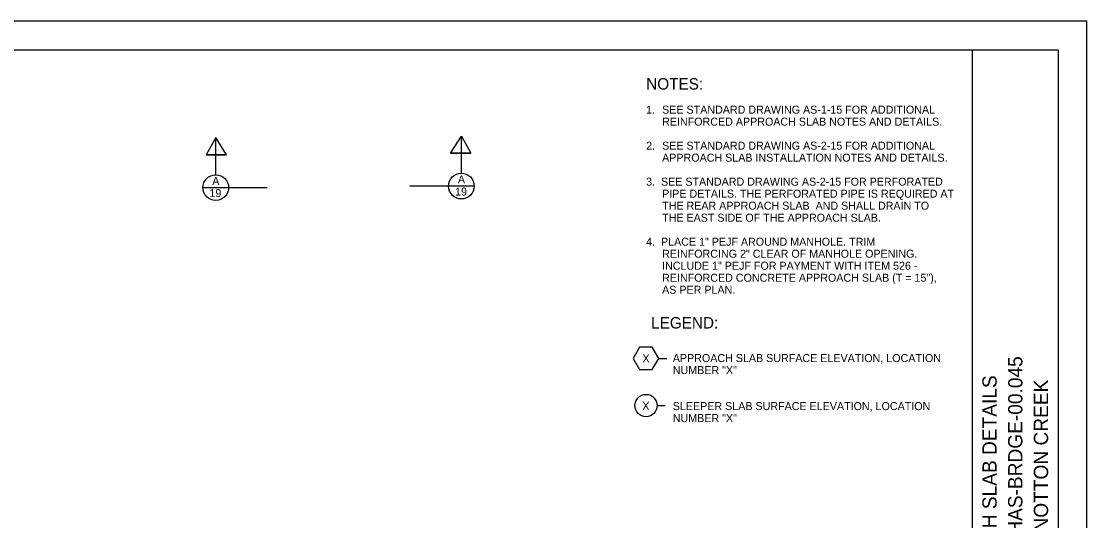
# Model space of a CAD drawing. Extents: x 0 to 34, y 0 to 22.
# Drawn here: x 15.36 to 34, y 13.27 to 22 of the extents above; entities that cross this region are included whole.
import ezdxf

# ---------------------------------------------------------------- set-up
doc = ezdxf.new("R2010")
doc.units = 0
for name, color, linetype in [('BR_P_Gen_Text', 7, 'Continuous'), ('SH_Border', 7, 'Continuous'), ('SH_Cut_Line', 7, 'Continuous'), ('SH_Data', 7, 'Continuous'), ('SH_Text', 7, 'Continuous')]:
    doc.layers.add(name, color=color, linetype=linetype)

msp = doc.modelspace()

# ---------------------------------------------------------------- linework, layer by layer
at = {"layer": 'BR_P_Gen_Text'}
msp.add_line((26.512, 16.105), (26.652, 16.105), dxfattribs=at)
msp.add_lwpolyline([(26.4, 16.3), (26.175, 16.3), (26.063, 16.105), (26.175, 15.91), (26.4, 15.91), (26.512, 16.105)], close=True, dxfattribs=at)
at = {"layer": 'SH_Border'}
msp.add_line((32, 0.5), (32, 21.5), dxfattribs=at)
msp.add_lwpolyline([(1.5, 21.5), (33.5, 21.5), (33.5, 0.5), (1.5, 0.5)], close=True, dxfattribs=at)
at = {"layer": 'SH_Cut_Line'}
msp.add_lwpolyline([(0, 0), (34, 0), (34, 22), (0, 22)], close=True, dxfattribs=at)
at = {"layer": 'SH_Text'}
for p, q in [((18.763, 19.967), (18.596, 19.666)), ((18.763, 19.967), (18.596, 19.666)), ((18.763, 19.316), (18.763, 19.967)), ((18.951, 19.666), (18.763, 19.967)), ((18.951, 19.666), (18.763, 19.967)), ((22.871, 19.693), (23.06, 19.994)), ((22.871, 19.693), (23.06, 19.994)), ((23.06, 19.343), (23.06, 19.994)), ((23.06, 19.994), (23.226, 19.693)), ((23.06, 19.994), (23.226, 19.693)), ((18.596, 19.666), (18.951, 19.666)), ((18.596, 19.666), (18.951, 19.666)), ((18.951, 19.666), (18.596, 19.666)), ((18.596, 19.666), (18.951, 19.666)), ((23.226, 19.693), (22.871, 19.693)), ((23.226, 19.693), (22.871, 19.693)), ((22.871, 19.693), (23.226, 19.693)), ((23.226, 19.693), (22.871, 19.693)), ((18.538, 19.091), (19.661, 19.091)), ((23.284, 19.118), (22.161, 19.118)), ((26.485, 15.279), (26.625, 15.279))]:
    msp.add_line(p, q, dxfattribs=at)
for centre, radius in [((18.763, 19.091), 0.225), ((23.06, 19.118), 0.225), ((26.291, 15.279), 0.195)]:
    msp.add_circle(centre, radius, dxfattribs=at)

# ---------------------------------------------------------------- texts
at = {"layer": 'BR_P_Gen_Text'}
msp.add_text('X', height=0.14, rotation=360, dxfattribs=at).set_placement((26.228, 16.035))
at = {"layer": 'SH_Data'}
for s, p in [('BRIDGE NO. HAS-BRDGE-00.045', (32.875, 10.958)), ('APPROACH SLAB DETAILS', (32.425, 11.498)), ('OVER CONOTTON CREEK', (33.325, 11.534))]:
    msp.add_text(s, height=0.25, rotation=90, dxfattribs=at).set_placement(p)
at = {"layer": 'SH_Text'}
for s, height, p in [('NOTES:', 0.2, (26.294, 20.806)), ('1.', 0.14, (26.292, 20.385)), ('SEE STANDARD DRAWING AS-1-15 FOR ADDITIONAL ', 0.14, (26.572, 20.385)), ('REINFORCED APPROACH SLAB NOTES AND DETAILS. ', 0.14, (26.572, 20.175)), ('2.', 0.14, (26.292, 19.755)), ('SEE STANDARD DRAWING AS-2-15 FOR ADDITIONAL ', 0.14, (26.572, 19.755)), ('APPROACH SLAB INSTALLATION NOTES AND DETAILS. ', 0.14, (26.572, 19.545)), ('A', 0.14, (18.702, 19.138)), ('A', 0.14, (22.999, 19.165)), ('3.  SEE STANDARD DRAWING AS-2-15 FOR PERFORATED   ', 0.14, (26.292, 19.125)), ('19', 0.14, (18.652, 18.925)), ('19', 0.14, (22.95, 18.952)), ('PIPE DETAILS. THE PERFORATED PIPE IS REQUIRED AT ', 0.14, (26.572, 18.915)), ('THE REAR APPROACH SLAB  AND SHALL DRAIN TO         ', 0.14, (26.572, 18.705)), ('THE EAST SIDE OF THE APPROACH SLAB.', 0.14, (26.572, 18.495)), ('4.  PLACE 1" PEJF AROUND MANHOLE. TRIM ', 0.14, (26.292, 18.075)), ('REINFORCING 2" CLEAR OF MANHOLE OPENING. ', 0.14, (26.572, 17.865)), ('INCLUDE 1" PEJF FOR PAYMENT WITH ITEM 526 - ', 0.14, (26.572, 17.655)), ('REINFORCED CONCRETE APPROACH SLAB (T = 15"), ', 0.14, (26.572, 17.445)), ('AS PER PLAN.', 0.14, (26.572, 17.235)), ('LEGEND:', 0.2, (26.38, 16.627)), ('APPROACH SLAB SURFACE ELEVATION, LOCATION     ', 0.14, (26.759, 16.04)), ('NUMBER "X"', 0.14, (26.759, 15.83)), ('SLEEPER SLAB SURFACE ELEVATION, LOCATION ', 0.14, (26.759, 15.2)), ('NUMBER "X"', 0.14, (26.759, 14.99))]:
    msp.add_text(s, height=height, dxfattribs=at).set_placement(p)
msp.add_text('X', height=0.14, rotation=180, dxfattribs=at).set_placement((26.351, 15.349))

doc.saveas('drawing.dxf')
